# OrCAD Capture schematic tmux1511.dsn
size A
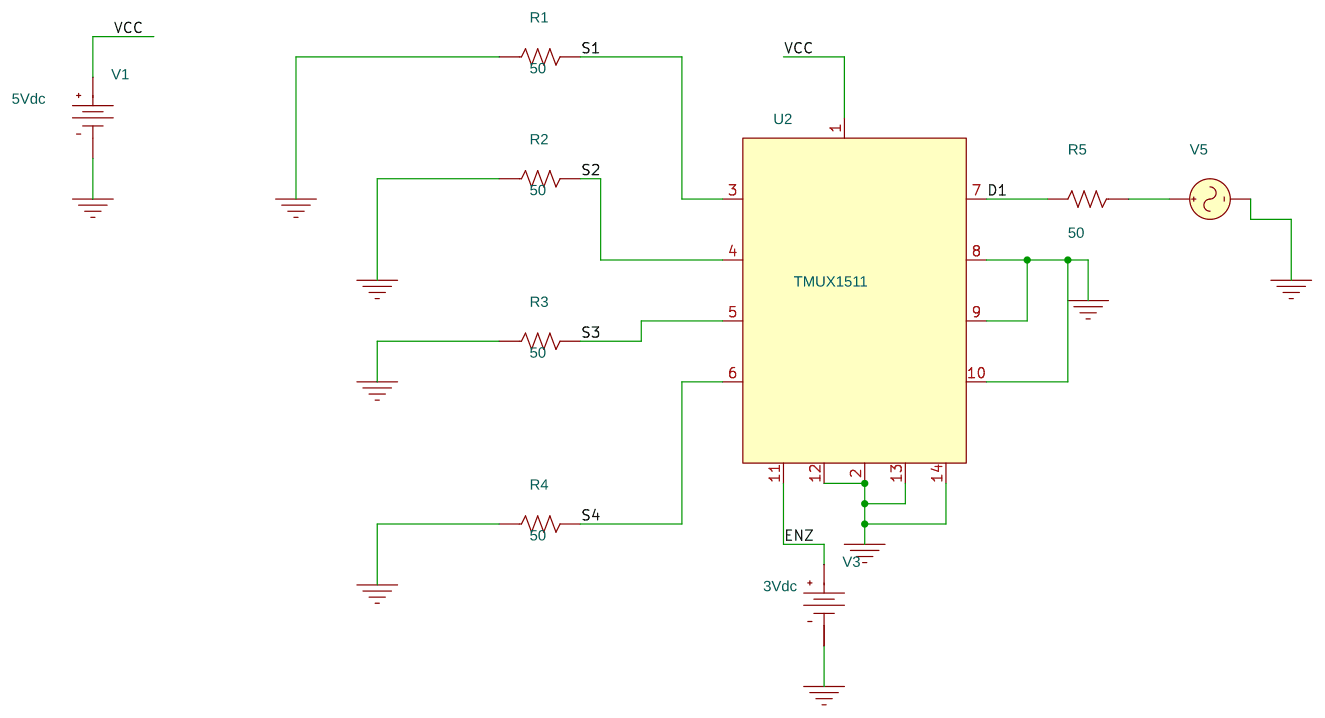
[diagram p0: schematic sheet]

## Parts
R1  50  [AX/RC05]
R2  50  [AX/RC05]
R3  50  [AX/RC05]
R4  50  [AX/RC05]
R5  50  [AX/RC05]
U2  TMUX1511
V1  VDC
V3  VDC
V5  VAC

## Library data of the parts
R1-R5 = R
U2 = TMUX1511
V1 = VDC: DC: 5Vdc
V3 = VDC: DC: 3Vdc
V5 = VAC

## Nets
VCC: U2.1(VCC) V1.0(+)
0: R1.1 R2.1 R3.1 R4.1 U2.2(GND) U2.8(D2) U2.9(D3) U2.10(D4) U2.12(SEL2) U2.13(SEL3) U2.14(SEL4) V1.1(-) V3.1(-) V5.2(-)
D1: R5.2 U2.7(D1)
ENZ: U2.11(SEL1) V3.0(+)
S1: R1.2 U2.3(S1)
S2: R2.2 U2.4(S2)
S3: R3.2 U2.5(S3)
S4: R4.2 U2.6(S4)
N32103: R5.1 V5.1(+)
